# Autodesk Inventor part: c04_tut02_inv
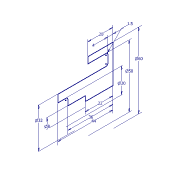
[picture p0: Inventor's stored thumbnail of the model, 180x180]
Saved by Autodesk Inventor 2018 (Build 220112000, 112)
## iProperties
Created: 2017-04
Part Number: c04_tut02_inv
Material: Generic
Document SubType Name: Modeling
Designer: CADCIM 00
Density: 1 g/cm^3
Appearance: Default
Author: CADCIM 00
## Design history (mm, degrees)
sketch "Sketch1"
  geometry: L1 (0, 0)-(-22, 0); L2 (-22, 0)-(-22, 4); L3 (-22, 4)-(-36, 4); L4 (-36, 4)-(-36, 8.5); L5 (-37.5, 10)-(-44, 10); L6 (-44, 10)-(-44, 16); L7 (-44, 16)-(-5.5, 16); L8 (-4, 17.5)-(-4, 23.5); L9 (-5.5, 25)-(-20, 25); L10 (-20, 25)-(-20, 30); L11 (-20, 30)-(0, 30); L12 (0, 30)-(0, 0); A1 r 1.5 centre (-5.5, 23.5) between (-4, 23.5) and (-5.5, 25); A2 r 1.5 centre (-37.5, 8.5) between (-36, 8.5) and (-37.5, 10); A3 r 1.5 centre (-5.5, 17.5) between (-5.5, 16) and (-4, 17.5)
  constraints: 24 end point, 11 perpendicular, 6 point on circle, 6 tangent, 3 centre point, 2 equal radius, 1 horizontal
  dimensions: "d0" = 8 diameter of L3 L1; "d1" = 20 diameter of L5 L1; "d2" = 32 diameter of L7 L1; "d3" = 50 diameter of L9 L1; "d4" = 60 diameter of L11 L1; "d5" = 4 distance between parallel lines of L8 L12; "d6" = 20 distance of L10.end L11.end; "d7" = 22 distance of L1.start L1.end; "d9" = 36 distance between parallel lines of L4 L12; "d10" = 44 distance between parallel lines of L12 L6; "d11" = 1.5 radius of A1
